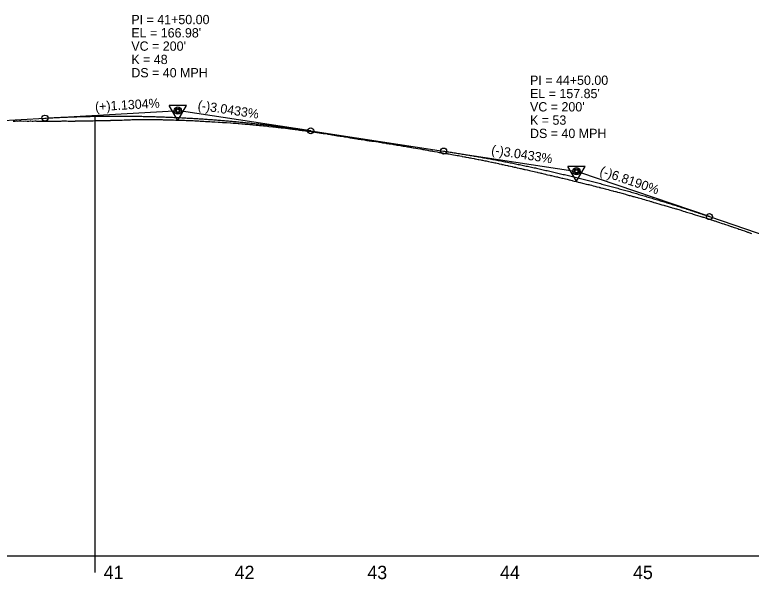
# Model space of a CAD drawing. Extents: x 1778432 to 1784301, y 601022 to 621789.
# Drawn here: x 1783170 to 1783724, y 621022 to 621446 of the extents above; entities that cross this region are included whole.
import ezdxf

# ---------------------------------------------------------------- set-up
doc = ezdxf.new("R2010")
doc.units = 0
for name, color, linetype in [('Exist Profile Cell', 7, 'Continuous'), ('Exist Vertical Profile Ground Line', 7, 'Continuous'), ('Exist Vertical Profile Horizontal Axis Label Major', 7, 'Continuous'), ('Prop PFL VPI Symbol CELL', 7, 'Continuous'), ('Prop Vertical Profile Curve Label', 7, 'Continuous'), ('Prop Vertical Profile Grade', 7, 'Continuous'), ('Prop Vertical Profile Grade Label', 7, 'Continuous'), ('Prop VPI Label', 7, 'Continuous'), ('Scratch_Level_1', 7, 'Continuous')]:
    doc.layers.add(name, color=color, linetype=linetype)

msp = doc.modelspace()

# ---------------------------------------------------------------- linework, layer by layer
at = {"layer": 'Exist Profile Cell'}
msp.add_line((1780142.96, 621039.19), (1784155.69, 621039.19), dxfattribs=at)
at = {"layer": 'Exist Vertical Profile Ground Line'}
msp.add_lwpolyline([(1783169.11, 621366.19), (1783170.54, 621366.23), (1783171.45, 621366.26), (1783172.02, 621366.15), (1783173.76, 621366.28), (1783174.97, 621366.36), (1783176.98, 621366.23), (1783178.61, 621366.41), (1783179.57, 621366.2), (1783180.19, 621366.18), (1783180.73, 621366.16), (1783181.76, 621366.34), (1783182.41, 621366.35), (1783183.41, 621366.14), (1783184.02, 621366.11), (1783185.23, 621366.27), (1783185.98, 621366.28), (1783186.63, 621366.22), (1783187.37, 621366.15), (1783188.66, 621366.2), (1783189.12, 621366.14), (1783189.84, 621366.2), (1783190.95, 621366.1), (1783192.07, 621366.18), (1783193.06, 621366.17), (1783193.37, 621366.17), (1783194.46, 621366.05), (1783195.51, 621366.17), (1783196.28, 621366.17), (1783197.05, 621366.17), (1783198.95, 621366.19), (1783199.5, 621366.19), (1783200.69, 621366.2), (1783201.51, 621366.12), (1783202.32, 621366.2), (1783202.71, 621366.21), (1783204.36, 621366.24), (1783205.09, 621366.21), (1783205.93, 621366.27), (1783207.93, 621366.26), (1783209.15, 621366.26), (1783210.36, 621366.1), (1783211.72, 621366.24), (1783212.54, 621366.22), (1783215.58, 621366.25), (1783215.92, 621366.26), (1783219.27, 621366.3), (1783220.94, 621366.37), (1783222.01, 621366.4), (1783222.88, 621366.41), (1783225.23, 621366.41), (1783225.99, 621366.41), (1783226.69, 621366.43), (1783228.45, 621366.47), (1783229.34, 621366.5), (1783230.3, 621366.51), (1783231.66, 621366.55), (1783232.69, 621366.58), (1783233.41, 621366.61), (1783234.2, 621366.62), (1783234.88, 621366.64), (1783236.02, 621366.66), (1783238.1, 621366.7), (1783238.68, 621366.64), (1783239.31, 621366.72), (1783241.32, 621366.75), (1783241.78, 621366.75), (1783242.25, 621366.71), (1783242.65, 621366.76), (1783244.53, 621366.79), (1783245.57, 621366.8), (1783245.95, 621366.82), (1783247.75, 621366.88), (1783248.55, 621366.9), (1783249.38, 621366.93), (1783251.14, 621366.95), (1783252.57, 621367.03), (1783253.18, 621367.05), (1783254.18, 621367.09), (1783255.86, 621367.16), (1783256.43, 621367.18), (1783257.4, 621367.22), (1783258.26, 621367.27), (1783259.13, 621367.29), (1783260.9, 621367.33), (1783262.4, 621367.34), (1783263.52, 621367.35), (1783263.83, 621367.35), (1783264.94, 621367.36), (1783265.35, 621367.37), (1783265.67, 621367.36), (1783267.05, 621367.36), (1783268.87, 621367.34), (1783270.27, 621367.35), (1783270.65, 621367.36), (1783272.16, 621367.34), (1783272.68, 621367.33), (1783273.48, 621367.34), (1783274.12, 621367.34), (1783275.42, 621367.31), (1783275.95, 621367.27), (1783276.7, 621367.29), (1783278.65, 621367.29), (1783279.92, 621367.28), (1783280.5, 621367.27), (1783281.22, 621367.27), (1783281.87, 621367.24), (1783283.14, 621367.16), (1783284.51, 621367.19), (1783285.1, 621367.18), (1783286.35, 621367.15), (1783288, 621367.11), (1783288.44, 621367.1), (1783289.57, 621367.06), (1783291.52, 621366.99), (1783291.87, 621366.97), (1783292.33, 621366.97), (1783292.79, 621366.94), (1783293.71, 621366.88), (1783294.76, 621366.88), (1783296, 621366.85), (1783296.39, 621366.83), (1783297.95, 621366.77), (1783299.22, 621366.69), (1783300.5, 621366.7), (1783301.14, 621366.67), (1783302.44, 621366.62), (1783303.73, 621366.57), (1783304.5, 621366.53), (1783305.65, 621366.46), (1783307.52, 621366.36), (1783308.47, 621366.31), (1783308.87, 621366.27), (1783309.73, 621366.17), (1783310.69, 621366.15), (1783312.09, 621366.08), (1783312.55, 621366.05), (1783313.85, 621365.97), (1783315.31, 621365.87), (1783316.67, 621365.81), (1783317.02, 621365.79), (1783318.58, 621365.66), (1783320.48, 621365.6), (1783320.78, 621365.56), (1783323.35, 621365.4), (1783324, 621365.4), (1783324.87, 621365.33), (1783326.51, 621365.23), (1783328.85, 621365.1), (1783329.33, 621365.05), (1783329.68, 621365.04), (1783332.47, 621364.86), (1783332.89, 621364.83), (1783334.71, 621364.7), (1783336.01, 621364.6), (1783337.06, 621364.53), (1783338.23, 621364.42), (1783339.19, 621364.35), (1783341.09, 621364.19), (1783342.33, 621364.09), (1783343.62, 621363.99), (1783345.49, 621363.84), (1783347.12, 621363.7), (1783348.98, 621363.52), (1783349.3, 621363.49), (1783351.79, 621363.24), (1783352.48, 621363.18), (1783353.4, 621363.08), (1783354.3, 621362.98), (1783354.98, 621362.91), (1783356.02, 621362.83), (1783357.46, 621362.66), (1783357.88, 621362.61), (1783358.19, 621362.58), (1783360.49, 621362.32), (1783361.55, 621362.2), (1783364.45, 621361.87), (1783365.09, 621361.8), (1783365.58, 621361.76), (1783366.79, 621361.65), (1783367.65, 621361.54), (1783368.51, 621361.43), (1783369.67, 621361.32), (1783370.3, 621361.25), (1783370.81, 621361.18), (1783373.91, 621360.8), (1783375.67, 621360.65), (1783377.31, 621360.43), (1783377.79, 621360.38), (1783379.24, 621360.22), (1783380.31, 621360.04), (1783381.21, 621359.91), (1783381.93, 621359.84), (1783382.78, 621359.76), (1783383.47, 621359.64), (1783384.45, 621359.48), (1783385.98, 621359.29), (1783386.57, 621359.22), (1783388.9, 621358.88), (1783390.02, 621358.72), (1783391.72, 621358.53), (1783392.96, 621358.31), (1783393.69, 621358.21), (1783394.17, 621358.15), (1783395.27, 621358.04), (1783396.13, 621357.88), (1783397.42, 621357.67), (1783398.29, 621357.56), (1783398.83, 621357.5), (1783399.28, 621357.42), (1783400.5, 621357.22), (1783402.38, 621356.95), (1783403.39, 621356.81), (1783405.24, 621356.49), (1783405.79, 621356.4), (1783406.36, 621356.31), (1783407.75, 621356.1), (1783408.82, 621355.91), (1783409.89, 621355.74), (1783410.51, 621355.64), (1783411.33, 621355.53), (1783411.96, 621355.4), (1783412.98, 621355.21), (1783415.13, 621354.92), (1783415.85, 621354.77), (1783417.5, 621354.5), (1783418.46, 621354.37), (1783418.94, 621354.3), (1783420.85, 621353.98), (1783421.59, 621353.85), (1783422.71, 621353.68), (1783423.63, 621353.55), (1783424.39, 621353.41), (1783425.85, 621353.16), (1783426.76, 621353.01), (1783427.72, 621352.85), (1783428.74, 621352.69), (1783430.9, 621352.4), (1783433.36, 621351.99), (1783434.1, 621351.87), (1783435.16, 621351.7), (1783436.11, 621351.55), (1783436.86, 621351.45), (1783438.39, 621351.23), (1783438.94, 621351.16), (1783439.53, 621351.08), (1783440.09, 621350.98), (1783441.88, 621350.75), (1783443.61, 621350.48), (1783444.64, 621350.31), (1783446.19, 621350.07), (1783446.99, 621349.94), (1783447.81, 621349.8), (1783449.35, 621349.53), (1783449.93, 621349.45), (1783451.4, 621349.24), (1783452.03, 621349.12), (1783452.61, 621349.04), (1783454.38, 621348.77), (1783455.35, 621348.6), (1783456.18, 621348.46), (1783457.63, 621348.17), (1783459.42, 621347.96), (1783461.18, 621347.62), (1783462.49, 621347.42), (1783462.93, 621347.33), (1783463.49, 621347.26), (1783465.67, 621346.89), (1783466.5, 621346.72), (1783467.58, 621346.59), (1783468.31, 621346.45), (1783468.85, 621346.36), (1783470.08, 621346.08), (1783472.02, 621345.83), (1783473.65, 621345.47), (1783475.44, 621345.24), (1783475.75, 621345.2), (1783477.23, 621344.86), (1783478.36, 621344.73), (1783479.01, 621344.59), (1783479.87, 621344.49), (1783480.81, 621344.3), (1783481.53, 621344.18), (1783482.57, 621343.92), (1783483.96, 621343.77), (1783484.37, 621343.69), (1783484.68, 621343.64), (1783486.14, 621343.26), (1783488.06, 621343.07), (1783489.71, 621342.66), (1783491.02, 621342.51), (1783492.11, 621342.33), (1783494.19, 621341.93), (1783495.73, 621341.71), (1783496.16, 621341.66), (1783496.73, 621341.55), (1783497.2, 621341.46), (1783499.06, 621341.11), (1783500.5, 621340.86), (1783501.81, 621340.6), (1783503.02, 621340.39), (1783504.08, 621340.19), (1783505.16, 621339.99), (1783506.56, 621339.7), (1783507.01, 621339.62), (1783508.62, 621339.31), (1783509.23, 621339.18), (1783509.71, 621339.09), (1783511.55, 621338.75), (1783512.52, 621338.57), (1783513.17, 621338.44), (1783514.3, 621338.24), (1783515.86, 621337.96), (1783516.52, 621337.83), (1783516.96, 621337.72), (1783519.05, 621337.3), (1783519.55, 621337.21), (1783520.98, 621336.93), (1783521.72, 621336.77), (1783522.26, 621336.68), (1783524.01, 621336.35), (1783524.87, 621336.17), (1783526.8, 621335.75), (1783528.97, 621335.33), (1783529.48, 621335.19), (1783531.51, 621334.78), (1783532.12, 621334.68), (1783533.21, 621334.45), (1783534.21, 621334.22), (1783534.85, 621334.09), (1783536.45, 621333.73), (1783536.86, 621333.63), (1783537.46, 621333.52), (1783539.29, 621333.13), (1783541.01, 621332.74), (1783541.59, 621332.61), (1783542, 621332.5), (1783543.25, 621332.24), (1783544.47, 621331.99), (1783545.12, 621331.84), (1783545.96, 621331.62), (1783546.96, 621331.43), (1783548.35, 621331.12), (1783549.72, 621330.83), (1783550.7, 621330.59), (1783551.2, 621330.49), (1783552.89, 621330.1), (1783553.27, 621330.02), (1783553.82, 621329.88), (1783554.26, 621329.78), (1783555.75, 621329.43), (1783557.49, 621329.1), (1783558.68, 621328.74), (1783559.93, 621328.5), (1783561.02, 621328.25), (1783562.09, 621328.02), (1783563.37, 621327.69), (1783563.92, 621327.59), (1783565.43, 621327.23), (1783566.06, 621327.05), (1783566.64, 621326.92), (1783568.37, 621326.51), (1783569.55, 621326.25), (1783570.08, 621326.12), (1783571.18, 621325.83), (1783572.78, 621325.51), (1783573.42, 621325.37), (1783574.04, 621325.22), (1783575.84, 621324.74), (1783576.51, 621324.62), (1783577.8, 621324.34), (1783578.55, 621324.13), (1783579.25, 621323.97), (1783580.14, 621323.74), (1783581.88, 621323.34), (1783582.74, 621323.13), (1783584.65, 621322.65), (1783585.89, 621322.42), (1783587.46, 621321.97), (1783588.6, 621321.72), (1783589.62, 621321.48), (1783590.17, 621321.32), (1783591.21, 621321.08), (1783592.67, 621320.71), (1783592.97, 621320.63), (1783594.14, 621320.33), (1783595.45, 621320.01), (1783595.78, 621319.93), (1783597.44, 621319.53), (1783598.57, 621319.28), (1783600.33, 621318.81), (1783601.49, 621318.58), (1783602.16, 621318.41), (1783603.07, 621318.13), (1783604.15, 621317.88), (1783605.46, 621317.56), (1783606.77, 621317.24), (1783608.3, 621316.85), (1783609.87, 621316.46), (1783610.33, 621316.35), (1783610.85, 621316.2), (1783611.24, 621316.1), (1783612.81, 621315.69), (1783614.48, 621315.3), (1783615.56, 621314.95), (1783616.85, 621314.64), (1783617.94, 621314.35), (1783619.01, 621314.07), (1783620.17, 621313.73), (1783620.79, 621313.59), (1783622.25, 621313.21), (1783622.56, 621313.12), (1783623.3, 621312.91), (1783623.86, 621312.76), (1783625.25, 621312.4), (1783627.09, 621311.92), (1783628, 621311.64), (1783629.71, 621311.17), (1783630.38, 621310.98), (1783631.07, 621310.78), (1783632.67, 621310.3), (1783633.38, 621310.14), (1783634.74, 621309.77), (1783635.36, 621309.58), (1783636.08, 621309.39), (1783637.7, 621308.94), (1783638.92, 621308.6), (1783639.37, 621308.47), (1783639.71, 621308.38), (1783640.52, 621308.14), (1783641.49, 621307.87), (1783642.79, 621307.52), (1783643.1, 621307.43), (1783644.22, 621307.09), (1783645.39, 621306.76), (1783646.53, 621306.43), (1783647.68, 621306.13), (1783648.94, 621305.78), (1783649.47, 621305.61), (1783651.25, 621305.05), (1783652.37, 621304.72), (1783655.52, 621303.8), (1783657.2, 621303.27), (1783658.71, 621302.9), (1783659.03, 621302.78), (1783659.44, 621302.69), (1783661.85, 621301.99), (1783663.35, 621301.54), (1783664.31, 621301.22), (1783665.02, 621301.03), (1783666.14, 621300.62), (1783667.6, 621300.29), (1783668.21, 621300.1), (1783670.73, 621299.36), (1783671.49, 621299.13), (1783673.22, 621298.49), (1783674.5, 621298.15), (1783675.05, 621297.94), (1783675.77, 621297.77), (1783677.67, 621297.16), (1783679.65, 621296.56), (1783680.3, 621296.34), (1783680.8, 621296.19), (1783682.11, 621295.69), (1783683.99, 621295.21), (1783685.74, 621294.57), (1783687.18, 621294.2), (1783687.55, 621294.06), (1783688.01, 621293.96), (1783688.64, 621293.8), (1783689.9, 621293.42), (1783690.43, 621293.26), (1783691.47, 621292.91), (1783691.94, 621292.74), (1783692.61, 621292.54), (1783694.36, 621291.94), (1783696.07, 621291.38), (1783696.65, 621291.19), (1783697.09, 621291.06), (1783699.04, 621290.44), (1783699.8, 621290.2), (1783700.47, 621289.97), (1783701.75, 621289.52), (1783702.53, 621289.26), (1783703.9, 621288.79), (1783704.41, 621288.62), (1783705.1, 621288.4), (1783706.85, 621287.83), (1783708.64, 621287.22), (1783709.21, 621287.01), (1783709.56, 621286.9), (1783711.52, 621286.22), (1783712.48, 621285.9), (1783714.23, 621285.27), (1783715.12, 621284.98), (1783716.32, 621284.58), (1783716.87, 621284.38), (1783717.62, 621284.12), (1783719.33, 621283.53), (1783721.07, 621282.93), (1783721.68, 621282.71), (1783722.02, 621282.6), (1783722.62, 621282.4), (1783724.74, 621281.62)], dxfattribs=at)
at = {"layer": 'Prop PFL VPI Symbol CELL'}
for p, q in [((1783292.97, 621366.6), (1783286.47, 621377.8)), ((1783299.42, 621377.8), (1783286.47, 621377.8)), ((1783292.97, 621366.6), (1783299.42, 621377.8)), ((1783592.97, 621320.95), (1783586.47, 621332.15)), ((1783599.42, 621332.15), (1783586.47, 621332.15)), ((1783592.97, 621320.95), (1783599.42, 621332.15))]:
    msp.add_line(p, q, dxfattribs=at)
for centre, radius in [((1783292.96, 621374.08), 1.75), ((1783292.96, 621374.08), 1.2), ((1783592.96, 621328.43), 1.75), ((1783592.96, 621328.43), 1.2)]:
    msp.add_circle(centre, radius, dxfattribs=at)
at = {"layer": 'Prop Vertical Profile Curve Label'}
for centre in [(1783192.96, 621368.43), (1783392.96, 621358.86), (1783492.96, 621343.65), (1783692.96, 621294.34)]:
    msp.add_circle(centre, 2.25, dxfattribs=at)
at = {"layer": 'Prop Vertical Profile Grade'}
for p, q in [((1782817.96, 621347.24), (1783192.96, 621368.43)), ((1783392.96, 621358.86), (1783492.96, 621343.65)), ((1783692.96, 621294.34), (1783897.96, 621224.46))]:
    msp.add_line(p, q, dxfattribs=at)
for points in [[(1783192.96, 621368.43), (1783196.96, 621368.65), (1783200.96, 621368.85), (1783204.96, 621369.03), (1783208.96, 621369.2), (1783212.96, 621369.35), (1783216.96, 621369.48), (1783220.96, 621369.6), (1783224.96, 621369.7), (1783228.96, 621369.79), (1783232.96, 621369.85), (1783236.96, 621369.9), (1783240.96, 621369.94), (1783244.96, 621369.96), (1783248.96, 621369.96), (1783252.96, 621369.94), (1783256.96, 621369.91), (1783260.96, 621369.86), (1783264.96, 621369.79), (1783268.96, 621369.71), (1783272.96, 621369.61), (1783276.96, 621369.49), (1783280.96, 621369.36), (1783284.96, 621369.21), (1783288.96, 621369.04), (1783292.96, 621368.86), (1783296.96, 621368.66), (1783300.96, 621368.45), (1783304.96, 621368.21), (1783308.96, 621367.96), (1783312.96, 621367.7), (1783316.96, 621367.41), (1783320.96, 621367.11), (1783324.96, 621366.8), (1783328.96, 621366.46), (1783332.96, 621366.11), (1783336.96, 621365.75), (1783340.96, 621365.36), (1783344.96, 621364.96), (1783348.96, 621364.55), (1783352.96, 621364.11), (1783356.96, 621363.66), (1783360.96, 621363.2), (1783364.96, 621362.71), (1783368.96, 621362.21), (1783372.96, 621361.7), (1783376.96, 621361.16), (1783380.96, 621360.61), (1783384.96, 621360.05), (1783388.96, 621359.46), (1783392.96, 621358.86)], [(1783492.96, 621343.65), (1783496.96, 621343.03), (1783500.96, 621342.4), (1783504.96, 621341.75), (1783508.96, 621341.09), (1783512.96, 621340.41), (1783516.96, 621339.72), (1783520.96, 621339.02), (1783524.96, 621338.29), (1783528.96, 621337.56), (1783532.96, 621336.81), (1783536.96, 621336.04), (1783540.96, 621335.26), (1783544.96, 621334.46), (1783548.96, 621333.65), (1783552.96, 621332.82), (1783556.96, 621331.98), (1783560.96, 621331.12), (1783564.96, 621330.25), (1783568.96, 621329.36), (1783572.96, 621328.45), (1783576.96, 621327.54), (1783580.96, 621326.6), (1783584.96, 621325.65), (1783588.96, 621324.69), (1783592.96, 621323.71), (1783596.96, 621322.72), (1783600.96, 621321.71), (1783604.96, 621320.69), (1783608.96, 621319.65), (1783612.96, 621318.59), (1783616.96, 621317.52), (1783620.96, 621316.44), (1783624.96, 621315.34), (1783628.96, 621314.23), (1783632.96, 621313.1), (1783636.96, 621311.95), (1783640.96, 621310.79), (1783644.96, 621309.62), (1783648.96, 621308.43), (1783652.96, 621307.22), (1783656.96, 621306), (1783660.96, 621304.77), (1783664.96, 621303.52), (1783668.96, 621302.25), (1783672.96, 621300.97), (1783676.96, 621299.68), (1783680.96, 621298.36), (1783684.96, 621297.04), (1783688.96, 621295.7), (1783692.96, 621294.34)]]:
    msp.add_spline(points, degree=3, dxfattribs=at)
at = {"layer": 'Prop VPI Label'}
for p, q in [((1783192.96, 621368.43), (1783290.21, 621373.92)), ((1783392.96, 621358.86), (1783295.68, 621373.66)), ((1783492.96, 621343.65), (1783590.24, 621328.84)), ((1783692.96, 621294.34), (1783595.56, 621327.54))]:
    msp.add_line(p, q, dxfattribs=at)
for centre in [(1783292.96, 621374.08), (1783592.96, 621328.43)]:
    msp.add_circle(centre, 2.75, dxfattribs=at)
at = {"layer": 'Scratch_Level_1'}
msp.add_line((1783230.71, 621026.69), (1783230.71, 621369.82), dxfattribs=at)

# ---------------------------------------------------------------- texts
at = {"layer": 'Exist Vertical Profile Horizontal Axis Label Major'}
for s, p in [('41', (1783237.19, 621021.69)), ('42', (1783335.73, 621021.69)), ('43', (1783435.57, 621021.69)), ('44', (1783535.41, 621021.69)), ('45', (1783635.5, 621021.69))]:
    msp.add_text(s, height=10, dxfattribs=at).set_placement(p)
at = {"layer": 'Prop Vertical Profile Curve Label'}
for s, p in [("VC = 200'", (1783257.96, 621419.08)), ('K = 48', (1783257.96, 621409.08)), ('DS = 40 MPH', (1783257.96, 621399.08)), ("VC = 200'", (1783557.96, 621373.43)), ('K = 53', (1783557.96, 621363.43)), ('DS = 40 MPH', (1783557.96, 621353.43))]:
    msp.add_text(s, height=7, dxfattribs=at).set_placement(p)
at = {"layer": 'Prop Vertical Profile Grade Label'}
for s, rotation, p in [('(+)1.1304%', 3.2336, (1783230.85, 621373.57)), ('(-)3.0433%', 351.3486, (1783307.57, 621374.89)), ('(-)3.0433%', 351.3486, (1783528.48, 621341.28)), ('(-)6.8190%', 341.1762, (1783609.83, 621325.85))]:
    msp.add_text(s, height=7, rotation=rotation, dxfattribs=at).set_placement(p)
at = {"layer": 'Prop VPI Label'}
for s, p in [('PI = 41+50.00', (1783257.96, 621439.08)), ("EL = 166.98'", (1783257.96, 621429.08)), ('PI = 44+50.00', (1783557.96, 621393.43)), ("EL = 157.85'", (1783557.96, 621383.43))]:
    msp.add_text(s, height=7, dxfattribs=at).set_placement(p)

doc.saveas('drawing.dxf')
